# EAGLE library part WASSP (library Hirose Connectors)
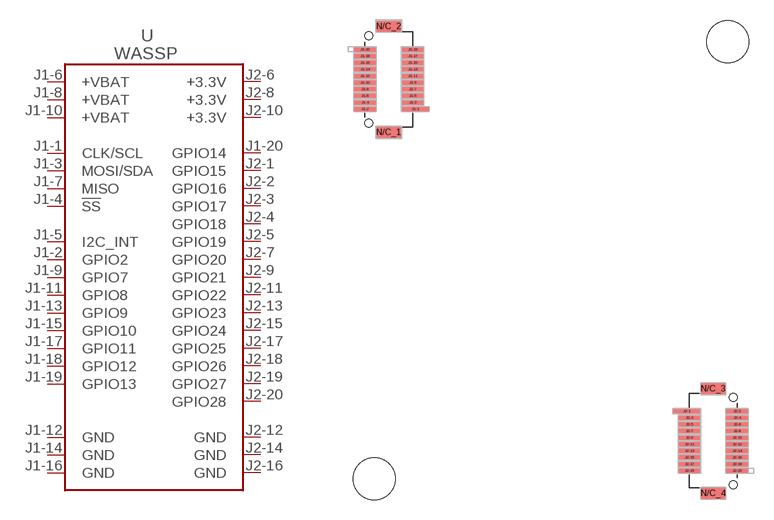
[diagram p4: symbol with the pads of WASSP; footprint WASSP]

Designator prefix U

## WASSP  [WASSP]
J1-1  CLK/SCL
J1-2  GPIO2
J1-3  MOSI/SDA
J1-4  !SS
J1-5  I2C_INT
J1-6  +VBAT
J1-7  MISO
J1-8  +VBAT
J1-9  GPIO7
J1-10  +VBAT
J1-11  GPIO8
J1-12  GND
J1-13  GPIO9
J1-14  GND
J1-15  GPIO10
J1-16  GND
J1-17  GPIO11
J1-18  GPIO12
J1-19  GPIO13
J1-20  GPIO14
J2-1  GPIO15
J2-2  GPIO16
J2-3  GPIO17
J2-4  GPIO18
J2-5  GPIO19
J2-6  +3.3V
J2-7  GPIO20
J2-8  +3.3V
J2-9  GPIO21
J2-10  +3.3V
J2-11  GPIO22
J2-12  GND
J2-13  GPIO23
J2-14  GND
J2-15  GPIO24
J2-16  GND
J2-17  GPIO25
J2-18  GPIO26
J2-19  GPIO27
J2-20  GPIO28

## Footprint WASSP (pad centres in mm)
smd 2 x 0.3: J1-1 5.632,30.455; J2-1 26.118,7.635
smd 1.6 x 0.3: J1-2 1.832,30.455; J1-3 5.432,30.955; J1-4 1.832,30.955; J1-5 5.432,31.455; J1-6 1.832,31.455; J1-7 5.432,31.955; J1-8 1.832,31.955; J1-9 5.432,32.455; J1-10 1.832,32.455; J1-11 5.432,32.955; J1-12 1.832,32.955; J1-13 5.432,33.455; J1-14 1.832,33.455; J1-15 5.432,33.955; J1-16 1.832,33.955; J1-17 5.432,34.455; J1-18 1.832,34.455; J1-19 5.432,34.955; J1-20 1.832,34.955; J2-2 29.918,7.635; J2-3 26.318,7.135; J2-4 29.918,7.135; J2-5 26.318,6.635; J2-6 29.918,6.635; J2-7 26.318,6.135; J2-8 29.918,6.135; J2-9 26.318,5.635; J2-10 29.918,5.635; J2-11 26.318,5.135; J2-12 29.918,5.135; J2-13 26.318,4.635; J2-14 29.918,4.635; J2-15 26.318,4.135; J2-16 29.918,4.135; J2-17 26.318,3.635; J2-18 29.918,3.635; J2-19 26.318,3.135; J2-20 29.918,3.135
smd 1.8 x 0.8: N/C_1 3.632,28.705; N/C_2 3.632,36.705; N/C_3 28.118,9.335; N/C_4 28.118,1.435
hole 3.175 at 2.54,2.54
hole 3.175 at 29.21,35.56
hole 0.61 at 2.132,29.405
hole 0.61 at 2.132,36.005
hole 0.61 at 29.618,8.685
hole 0.61 at 29.618,2.085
